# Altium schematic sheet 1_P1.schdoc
size 309 x 223 mm; Symbol: Sheet-Symbol_A4; Device: Sheet-Symbol_A4; @Page Name: P1; @Create Date: 2023-06-23; @Page Count: 1; @Page No: 1; @Project Name: usrp2040-series; @Schematic Name: USB2Protocol; @Update Date: 2023-06-23; Company: 嘉立创EDA; Page Size: A4; Version: V1.0
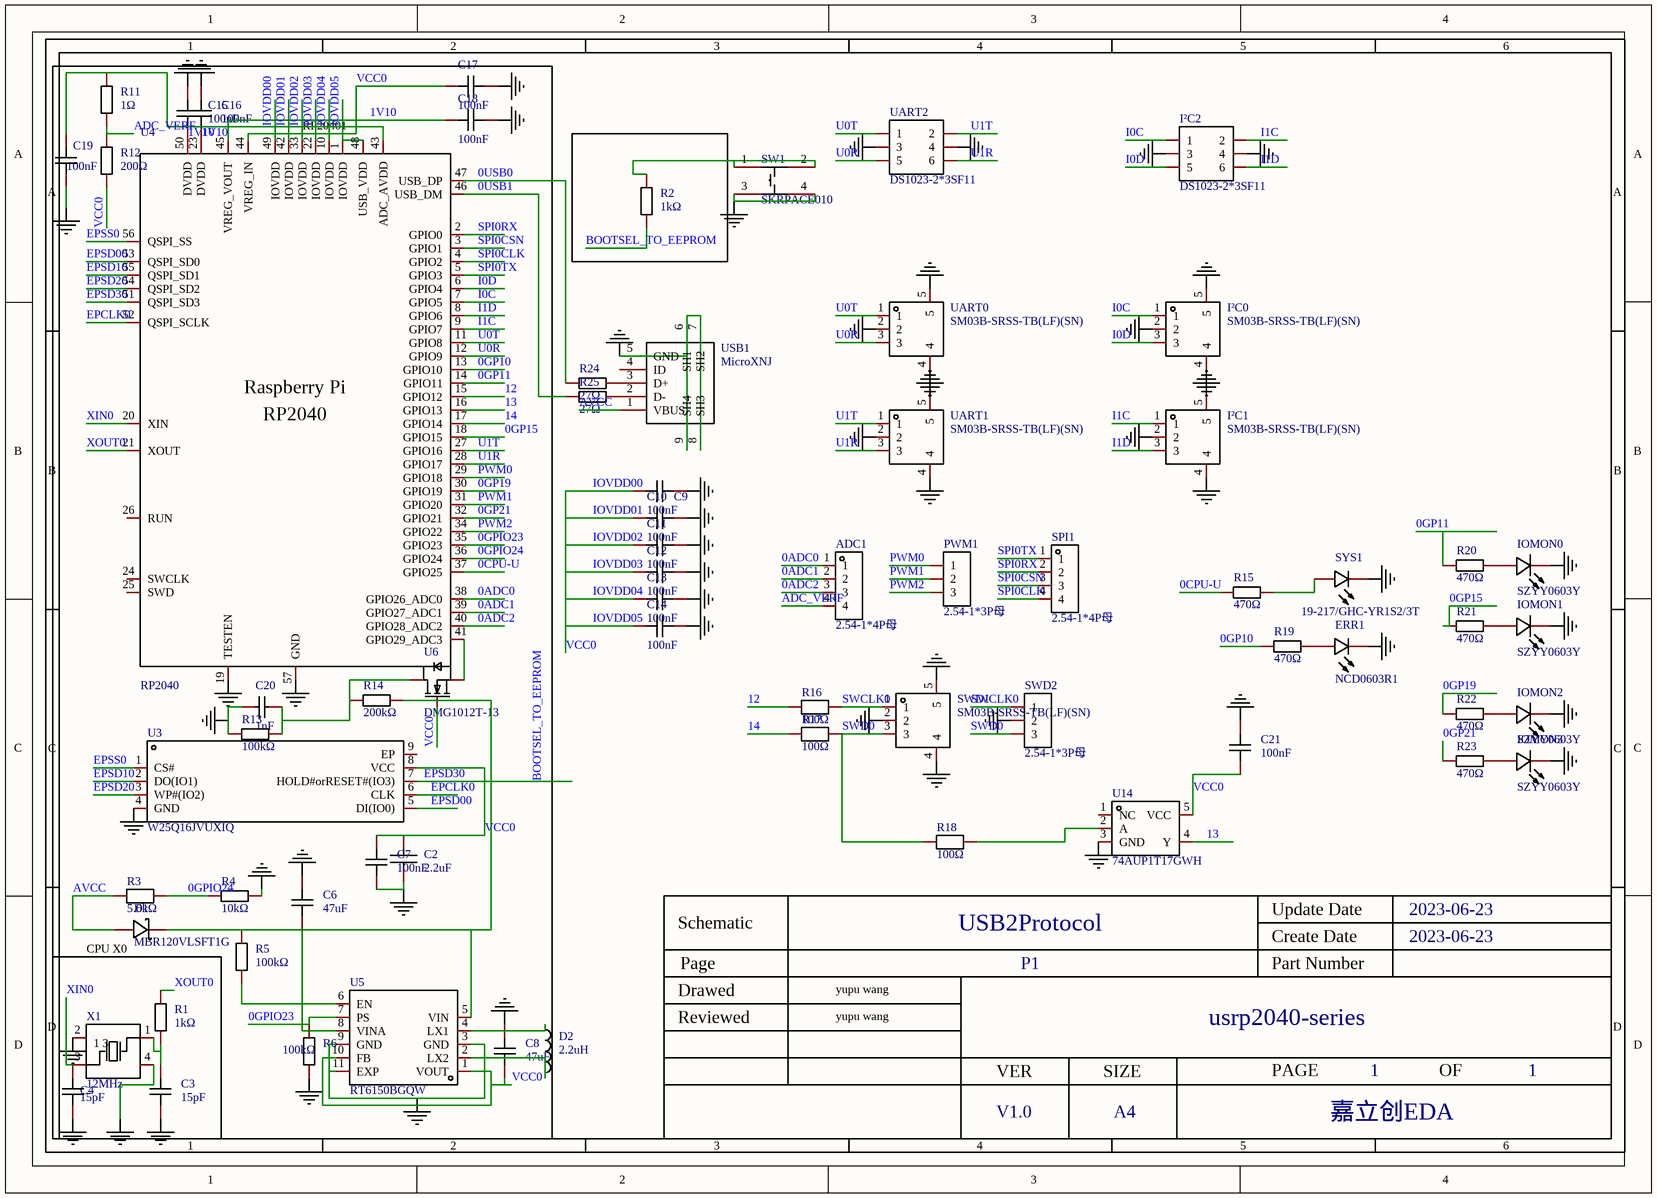
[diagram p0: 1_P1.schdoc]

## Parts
ADC1  2.54-1*4P母  [HDR-TH_4P-P2.54-V-F]
C2  2.2uF  [C0402]
C3  15pF  [C0201]
C4  15pF  [C0201]
C6  47uF  [C0805]
C7  100nF  [C0201]
C8  47uF  [C0805]
C9  100nF  [C0201]
C10  100nF  [C0201]
C11  100nF  [C0201]
C12  100nF  [C0201]
C13  100nF  [C0201]
C14  100nF  [C0201]
C15  100nF  [C0201]
C16  100nF  [C0201]
C17  100nF  [C0201]
C18  100nF  [C0201]
C19  100nF  [C0201]
C20  1nF  [C0201]
C21  100nF  [C0201]
D1  MBR120VLSFT1G  [SOD-123F_L2.8-W1.8-LS3.7-RD]
D2  2.2uH  [IND-SMD_L2.5-W2.0]
ERR1  NCD0603R1  [LED0603-RD_RED]
IOMON0  SZYY0603Y  [LED0603-R-RD_YELLOW]
IOMON1  SZYY0603Y  [LED0603-R-RD_YELLOW]
IOMON2  SZYY0603Y  [LED0603-R-RD_YELLOW]
IOMON3  SZYY0603Y  [LED0603-R-RD_YELLOW]
I²C0  SM03B-SRSS-TB(LF)(SN)  [CONN-SMD_SM03B-SRSS-TB-LF-SN-P]
I²C1  SM03B-SRSS-TB(LF)(SN)  [CONN-SMD_SM03B-SRSS-TB-LF-SN-P]
I²C2  DS1023-2*3SF11  [HDR-TH_6P-P2.54-V-F-R2-C3-S2.54]
PWM1  2.54-1*3P母  [HDR-TH_3P-P2.54-V-F]
R1  1kΩ  [R0402]
R2  1kΩ  [R0402]
R3  5.6kΩ  [R0402]
R4  10kΩ  [R0603]
R5  100kΩ  [R0402]
R6  100kΩ  [R0402]
R11  1Ω  [R0402]
R12  200Ω  [R0603]
R13  100kΩ  [R0402]
R14  200kΩ  [R0402]
R15  470Ω  [R0402]
R16  100Ω  [R0402]
R17  100Ω  [R0402]
R18  100Ω  [R0402]
R19  470Ω  [R0402]
R20  470Ω  [R0402]
R21  470Ω  [R0402]
R22  470Ω  [R0402]
R23  470Ω  [R0402]
R24  27Ω  [R0201]
R25  27Ω  [R0201]
SPI1  2.54-1*4P母  [HDR-TH_4P-P2.54-V-F]
SW1  SKRPACE010  [KEY-SMD_4P-L4.2-W3.2-P2.20-LS4.6]
SWD1  SM03B-SRSS-TB(LF)(SN)  [CONN-SMD_SM03B-SRSS-TB-LF-SN-P]
SWD2  2.54-1*3P母  [HDR-TH_3P-P2.54-V-F]
SYS1  19-217/GHC-YR1S2/3T  [LED0603-RD]
U3  W25Q16JVUXIQ  [USON-8_L3.0-W2.0-P0.50-BL-EP]
U4  RP2040  [LQFN-56_L7.0-W7.0-P0.4-EP]
U5  RT6150BGQW  [WSON-10_L2.5-W2.5-P0.50-BL-EP]
U6  DMG1012T-13  [SOT-523-3_L1.6-W0.8-P1.00-LS1.6-BR]
U14  74AUP1T17GWH  [TSSOP-5_L2.1-W1.3-P0.65-LS2.2-BR]
UART0  SM03B-SRSS-TB(LF)(SN)  [CONN-SMD_SM03B-SRSS-TB-LF-SN-P]
UART1  SM03B-SRSS-TB(LF)(SN)  [CONN-SMD_SM03B-SRSS-TB-LF-SN-P]
UART2  DS1023-2*3SF11  [HDR-TH_6P-P2.54-V-F-R2-C3-S2.54]
USB1  MicroXNJ  [MICRO-USB-SMD_MICROXNJ]
X1  12MHz  [CRYSTAL-SMD_4P-L3.2-W2.5-BL]

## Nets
NetC2_2: C2.2 C3.1 C4.1 C6.1 C7.1 C8.2 C9.2 C10.2 C11.2 C12.2 C13.2 C14.2 C15.1 C16.2 C17.1 C18.1 C19.1 C20.1 C21.2 ERR1.1(K) IOMON0.2(-) IOMON1.2(-) IOMON2.2(-) IOMON3.2(-) I²C0.2 I²C0.4 I²C0.5 I²C1.2 I²C1.4 I²C1.5 I²C2.3 I²C2.4 R4.2 R6.1 R13.1 SW1.3 SW1.4 SWD1.2 SWD1.4 SWD1.5 SWD2.2 SYS1.1(C) U3.4(GND) U4.19(TESTEN) U4.57(GND) U5.3(GND) U5.9(GND) U5.11(EXP) U14.3(GND) UART0.2 UART0.4 UART0.5 UART1.2 UART1.4 UART1.5 UART2.3 UART2.4 USB1.5(GND) USB1.6(SH1) USB1.7(SH2) USB1.8(SH3) USB1.9(SH4) X1.2(GND) X1.4(GND)
0ADC0: ADC1.1 U4.38(GPIO26_ADC0)
0ADC1: ADC1.2 U4.39(GPIO27_ADC1)
0ADC2: ADC1.3 U4.40(GPIO28_ADC2)
0CPU-U: R15.1 U4.37(GPIO25)
0GP10: R19.1 U4.13(GPIO10)
0GP11: R20.1 U4.14(GPIO11)
0GP15: R21.1 U4.18(GPIO15)
0GP19: R22.1 U4.30(GPIO19)
0GP21: R23.1 U4.32(GPIO21)
0GPIO23: R6.2 U4.35(GPIO23) U5.7(PS)
0GPIO24: R3.1 R4.1 U4.36(GPIO24)
0USB0: R24.1 U4.47(USB_DP)
0USB1: R25.1 U4.46(USB_DM)
1V10: C15.2 C16.1 C18.2 U4.23(DVDD) U4.45(VREG_VOUT) U4.50(DVDD)
12: R16.1 U4.15(GPIO12)
13: U4.16(GPIO13) U14.4(Y)
14: R17.1 U4.17(GPIO14)
ADC_VERF: ADC1.4 R11.1 R12.2
AVCC: D1.2(A) R3.2 USB1.1(VBUS)
BOOTSEL_TO_EEPROM: R2.1 U3.7(HOLD#orRESET#(IO3)) U4.51(QSPI_SD3)  [also labelled EPSD30]
EPCLK0: U3.6(CLK) U4.52(QSPI_SCLK)
EPSD00: U3.5(DI(IO0)) U4.53(QSPI_SD0)
EPSD10: U3.2(DO(IO1)) U4.55(QSPI_SD1)
EPSD20: U3.3(WP#(IO2)) U4.54(QSPI_SD2)
EPSS0: U3.1(CS#) U4.56(QSPI_SS)
I0C: I²C0.1 I²C2.1 U4.7(GPIO5)
I0D: I²C0.3 I²C2.5 U4.6(GPIO4)
I1C: I²C1.1 I²C2.2 U4.9(GPIO7)
I1D: I²C1.3 I²C2.6 U4.8(GPIO6)
IOVDD00: C2.1 C7.2 C8.1 C9.1 C10.1 C11.1 C12.1 C13.1 C14.1 C17.2 C19.2 C21.1 R11.2 R12.1 U3.8(VCC) U4.1(IOVDD) U4.10(IOVDD) U4.22(IOVDD) U4.33(IOVDD) U4.42(IOVDD) U4.43(ADC_AVDD) U4.44(VREG_IN) U4.48(USB_VDD) U4.49(IOVDD) U5.1(VOUT) U5.10(FB) U6.1(G) U14.5(VCC)  [also labelled IOVDD01, IOVDD02, IOVDD03, IOVDD04, IOVDD05, VCC0]
PWM0: PWM1.1 U4.29(GPIO18)
PWM1: PWM1.2 U4.31(GPIO20)
PWM2: PWM1.3 U4.34(GPIO22)
SPI0CLK: SPI1.4 U4.4(GPIO2)
SPI0CSN: SPI1.3 U4.3(GPIO1)
SPI0RX: SPI1.2 U4.2(GPIO0)
SPI0TX: SPI1.1 U4.5(GPIO3)
SWCLK0: R16.2 SWD1.1 SWD2.1
SWD0: R17.2 R18.1 SWD1.3 SWD2.3
U0R: U4.12(GPIO9) UART0.3 UART2.5
U0T: U4.11(GPIO8) UART0.1 UART2.1
U1R: U4.28(GPIO17) UART1.3 UART2.6
U1T: U4.27(GPIO16) UART1.1 UART2.2
XIN0: C4.2 U4.20(XIN) X1.3(OSC2)
XOUT0: R1.2 U4.21(XOUT)
NetC3_2: C3.2 R1.1 X1.1(OSC1)
NetC6_2: C6.2 D1.1(K) R5.2 R14.2 U5.5(VIN) U5.8(VINA)
NetC20_2: C20.2 R13.2 R14.1 U6.3(D)
NetD2_1: D2.1 U5.4(LX1)
NetD2_2: D2.2 U5.2(LX2)
NetERR1_2: ERR1.2(A) R19.2
NetIOMON0_1: IOMON0.1(+) R20.2
NetIOMON1_1: IOMON1.1(+) R21.2
NetIOMON2_1: IOMON2.1(+) R22.2
NetIOMON3_1: IOMON3.1(+) R23.2
NetR2_2: R2.2 SW1.1 SW1.2
NetR5_1: R5.1 U5.6(EN)
NetR15_2: R15.2 SYS1.2(A)
NetR18_2: R18.2 U14.2(A)
NetR24_2: R24.2 USB1.3(D+)
NetR25_2: R25.2 USB1.2(D-)
NetU4_41: U4.41(GPIO29_ADC3) U6.2(S)

Not connected (* = marked no-connect by the designer): U3 9(EP); U4 24(SWCLK) 25(SWD) 26(RUN); U14 1(NC); USB1 4(ID)

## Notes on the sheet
- (near U4) RP20401
- (near D1) CPU X0
- yupu wang
- (near X1) 1 3

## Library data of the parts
ADC1 SPI1 = 2.54-1*4P母: 排数:单排;总孔位数:4;间距:2.54mm;插孔结构:1x4P;行距:-;安装类型:直插;圆孔/方孔:方孔;额定电流:3A;额定电压:-;插孔方向:顶部;塑高:-;触头材质:青铜;触头镀层:-;工作温度范围:-40℃~+105℃;焊接温度(最大值):-;; Manufacturer: BOOMELE(博穆精密); Add into BOM: yes; Number of Holes: 4; Pitch: 2.54mm; Holes Structure: 1x4P; Circular Hole / Square Hole: 方孔; Current Rating (Max): 3A; Holes Direction: 顶部
C2 = CL05A225MQ5NSNC: 容值:2.2uF;精度:±20%;额定电压:6.3V;材质(温度系数):X5R;; Manufacturer: SAMSUNG(三星); Add into BOM: yes; Tolerance: ±20%; Voltage Rated: 6.3V; Temperature Coefficient: X5R
C3 C4 = CL03C150JA3ANNC: 容值:15pF;精度:±5%;额定电压:25V;材质(温度系数):C0G;; Manufacturer: SAMSUNG(三星); Add into BOM: yes; Tolerance: ±5%; Voltage Rated: 25V; Temperature Coefficient: C0G
C6 C8 = GRM21BR60J476ME01L: 容值:47uF;精度:±20%;额定电压:6.3V;材质(温度系数):X5R;; Manufacturer: muRata(村田); Add into BOM: yes; Tolerance: ±20%; Voltage Rated: 6.3V; Temperature Coefficient: X5R
C7 C9-C19 C21 = GRM033R60J104KE19D: 容值:100nF;精度:±10%;额定电压:6.3V;材质(温度系数):X5R;; Manufacturer: muRata(村田); Add into BOM: yes; Tolerance: ±10%; Voltage Rated: 6.3V; Temperature Coefficient: X5R
C20 = GRM033R71E102KA01D: 容值:1nF;精度:±10%;额定电压:25V;材质(温度系数):X7R;; Manufacturer: muRata(村田); Add into BOM: yes; Tolerance: ±10%; Voltage Rated: 25V; Temperature Coefficient: X7R
D1 = MBR120VLSFT1G: 直流反向耐压(Vr):20V;平均整流电流(Io):1A;正向压降(Vf):300mV@1A;; Manufacturer: onsemi(安森美); Add into BOM: yes; Reverse Voltage (Vr): 20V; Average Rectified Current (Io): 1A
D2 = SRN2512-2R2M: 电感值:2.2uH;精度:±20%;额定电流:2.3A;饱和电流(Isat):2.7A;直流电阻(DCR):102mΩ;; Manufacturer: BOURNS; Add into BOM: yes; Tolerance: ±20%; Rated Current: 2.3A; Saturation Current (Isat): 2.7A; DC Resistance (DCR): 102mΩ; Q @ Freq: 11@1MHz; Frequency - Self Resonant: 80MHz
ERR1 = NCD0603R1_C84263: 发光颜色:红灯;; Manufacturer: 国星光电; Symbol: FC-DA1608HRK-620D; Add into BOM: yes; Emitted Color: 红灯
IOMON0-IOMON3 = SZYY0603Y: 发光颜色:黄灯;二极管配置:-;主波长:584nm~594nm;色温:-;功率:40mW;安装方式:-;; Manufacturer: yongyu(永裕光电); Add into BOM: yes; Emitted Color: 黄灯; Lens Color: 无色透明; Peak Wavelength: 596nm; Forward Current: 10mA; Power Dissipation: 40mW; Viewing Angle: 120°
I²C0 I²C1 SWD1 UART0 UART1 = SM03B-SRSS-TB(LF)(SN): 参考系列:SR/SZ;间距:1mm;插针结构:1x3P;排数:1;每排PIN数:3;行距:-;安装方式:-;触头材质:铜合金;; Manufacturer: JST; Symbol: SM03B-SRSS-TB(LF)(SN)(P); Add into BOM: yes; Reference Series: SR/SZ; Pitch: 1mm; Pins Structure: 1x3P; Number of PINs Per Row: 3
I²C2 UART2 = DS1023-2*3SF11: 排数:双排;总孔位数:6;间距:2.54mm;插孔结构:2x3P;行距:2.54mm;安装类型:直插;塑高:-;触头材质:-;触头镀层:-;; Manufacturer: CONNFLY; Symbol: Header-Female-2.54_2x3; Add into BOM: yes; Number of Holes: 6; Pitch: 2.54mm; Holes Structure: 2x3P
PWM1 SWD2 = 2.54-1*3P母: 排数:单排;总孔位数:3;间距:2.54mm;行距:-;安装类型:直插;塑高:-;触头材质:-;触头镀层:金;; Manufacturer: BOOMELE(博穆精密); Symbol: Header-Female-2.54_1x3; Add into BOM: yes; Number of Holes: 3; Pitch: 2.54mm
R1 R2 = AECR0402F1K00K9: 电阻类型:厚膜电阻;阻值:1kΩ;精度:±1%;功率:63mW;; Manufacturer: RESI(开步睿思）; Add into BOM: yes; Tolerance: ±1%; Power(Watts): 63mW; Temperature Coefficient: ±100ppm/℃; Overload Voltage (Max): 50V
R3 = CR0402F5K60Q10Z: 阻值:5.6kΩ;精度:±1%;功率:63mW;; Manufacturer: EVER OHMS(天二科技); Add into BOM: yes; Tolerance: ±1%; Power(Watts): 63mW; Temperature Coefficient: ±100ppm/℃
R4 = 0603WAF1002T5E: 电阻类型:厚膜电阻;阻值:10kΩ;精度:±1%;功率:100mW;; Manufacturer: UNI-ROYAL(厚声); Add into BOM: yes; Tolerance: ±1%; Power(Watts): 100mW; Temperature Coefficient: ±100ppm/℃; Overload Voltage (Max): 75V
R5 R6 R13 = RC0402FR-07100KL: 电阻类型:厚膜电阻;阻值:100kΩ;精度:±1%;功率:62.5mW;; Manufacturer: YAGEO(国巨); Add into BOM: yes; Tolerance: ±1%; Power(Watts): 62.5mW; Temperature Coefficient: ±100ppm/℃; Overload Voltage (Max): 50V
R11 = RC0402FR-071RL: 电阻类型:厚膜电阻;阻值:1Ω;精度:±1%;功率:62.5mW;; Manufacturer: YAGEO(国巨); Add into BOM: yes; Tolerance: ±1%; Power(Watts): 62.5mW; Temperature Coefficient: ±200ppm/℃; Overload Voltage (Max): 50V
R12 = RC0603FR-07200RL: 电阻类型:厚膜电阻;阻值:200Ω;精度:±1%;功率:100mW;; Manufacturer: YAGEO(国巨); Add into BOM: yes; Tolerance: ±1%; Power(Watts): 100mW; Temperature Coefficient: ±100ppm/℃; Overload Voltage (Max): 75V
R14 = RC0402FR-07200KL: 电阻类型:厚膜电阻;阻值:200kΩ;精度:±1%;功率:62.5mW;; Manufacturer: YAGEO(国巨); Add into BOM: yes; Tolerance: ±1%; Power(Watts): 62.5mW; Temperature Coefficient: ±100ppm/℃; Overload Voltage (Max): 50V
R15 R19-R23 = RC0402FR-07470RL: 电阻类型:厚膜电阻;阻值:470Ω;精度:±1%;功率:62.5mW;; Manufacturer: YAGEO(国巨); Add into BOM: yes; Tolerance: ±1%; Power(Watts): 62.5mW; Temperature Coefficient: ±100ppm/℃; Overload Voltage (Max): 50V
R16-R18 = CR0402F100RQ10Z: 阻值:100Ω;精度:±1%;功率:63mW;; Manufacturer: EVER OHMS(天二科技); Add into BOM: yes; Tolerance: ±1%; Power(Watts): 63mW; Temperature Coefficient: ±100ppm/℃
R24 R25 = RC0201FR-0727RL: 电阻类型:厚膜电阻;阻值:27Ω;精度:±1%;功率:50mW;; Manufacturer: YAGEO(国巨); Add into BOM: yes; Tolerance: ±1%; Power(Watts): 50mW; Temperature Coefficient: ±200ppm/℃; Overload Voltage (Max): 25V
SW1 = SKRPACE010: 触点电流:50mA;额定电压(DC):16V;电路结构:单刀单掷;安装方式:立贴;带灯:-;机械寿命:-;; Manufacturer: ALPSALPINE(阿尔卑斯阿尔派); Add into BOM: yes; Contact Current: 50mA; Voltage Rating (DC): 16V; Circuit: 单刀单掷; Actuator Style: 椭圆形按钮; Switch Length: 4.2mm; Switch Width: 3.2mm; Switch Height: 2.5mm
SYS1 = 19-217/GHC-YR1S2/3T: 发光颜色:翠绿;二极管配置:-;主波长:520nm~535nm;色温:-;功率:110mW;安装方式:-;; Manufacturer: EVERLIGHT(亿光); Add into BOM: yes; Emitted Color: 翠绿; Lens Color: 无色透明; Peak Wavelength: 518nm; Forward Current: 20mA; Power Dissipation: 110mW; Viewing Angle: 120°
U3 = W25Q16JVUXIQ: Manufacturer: WINBOND(华邦); Add into BOM: no; Convert to PCB: yes
U4 = RP2040_C2040: 应用领域:-;CPU内核:ARM-M系列;CPU最大主频:133MHz;工作电压范围:-;程序存储容量:-;程序存储器类型:-;RAM总容量:264KB;GPIO端口数量:30;; Manufacturer: Raspberry Pi(树莓派); Add into BOM: no; Convert to PCB: yes; CPU Maximum Speed: 133MHz; RAM Size: 264KB; GPIO Ports Number: 30; ADC (Bit): 12bit; UART/USART: 2; Universal Serial Bus: 有; Peripheral/Function: DMA；PWM
U5 = RT6150BGQW: 功能类型:升降压型;同步整流:是;输出通道数:1;拓扑结构:降压-升压式;输入电压:1.8V~5.5V;输出电压:1.8V~5.5V;输出电流(最大值):800mA;开关频率:1MHz;; Manufacturer: RICHTEK(立锜); Add into BOM: yes; Function: 升降压型; Synchronous Rectification: 是; Number of Outputs: 1; Topology: 降压-升压式; Output Current (Max): 800mA; Switching Frequency: 1MHz
U6 = DMG1012T-13: 类型:N沟道;漏源电压(Vdss):20V;连续漏极电流(Id):630mA;功率(Pd):280mW;导通电阻(RDS(on)@Vgs,Id):400mΩ@600mA,4.5V;; Manufacturer: DIODES(美台); Add into BOM: yes; Drain Source Voltage (Vdss): 20V; Continuous Drain Current (Id): 630mA; Power Dissipation (Pd): 280mW; Gate Threshold Voltage (Vgs(th)@Id): 1V@250uA; Total Gate Charge (Qg@Vgs): 737pC@4.5V; Input Capacitance (Ciss@Vds): 60.67pF@16V
U14 = 74AUP1T17GWH: 逻辑电路的归属系列:-;逻辑类型:-;元件数:-;每元件位数:-;; Manufacturer: Nexperia(安世); Add into BOM: yes
USB1 = MicroXNJ: 连接器类型:Micro-B;标准:USB 2.0;公母:母座;触点数量:5;端口数量:1;安装方式:卧贴;额定电流 - 电源:1A;工作温度范围:-20℃~+85℃;; Manufacturer: SHOU HAN(首韩); Add into BOM: yes; Gender: 母座; Number of Contacts: 5; Number of Ports: 1; Current Rating - Power (Max): 1A
X1 = X322512MMB4SI: 频率:12MHz;频率公差:±10ppm;负载电容:10pF;; Manufacturer: YXC(扬兴晶振); Add into BOM: yes; Crystal Type: 贴片无源晶振; Frequency Tolerance: ±10ppm; Frequency Stability: ±30ppm; Load Capacitance: 10pF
